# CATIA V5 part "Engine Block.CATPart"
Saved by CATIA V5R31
Part number: Part1
Bounding box of the stored display mesh (mm): x 0 to 150, y 0 to 40, z 0 to 43
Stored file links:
  D:\PROJECTS\Project 2021\US EDITION\CATIA V5 6R 2021\Resources\Tutorial Files\c19_catia_v5_6r2021_tut\C19_tut_04.CATPart\Engine Block.CATPart
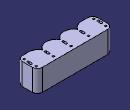
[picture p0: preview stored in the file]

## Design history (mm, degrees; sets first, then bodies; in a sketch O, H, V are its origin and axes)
Body1 (main body)
  Sketch1 on xy-plane, origin (0, 0, 0), H (1, 0, 0), V (0, 1, 0)
    line L1 (10, 0) -> (140, 0)
    line L2 (150, 10) -> (150, 30)
    line L3 (140, 40) -> (10, 40)
    line L4 (0, 30) -> (0, 10)
    arc A1 centre (10, 10) radius 10 from (10, 0) to (0, 10) cw
    arc A2 centre (140, 10) radius 10 from (140, 0) to (150, 10) ccw
    arc A3 centre (140, 30) radius 10 from (150, 30) to (140, 40) ccw
    arc A4 centre (10, 30) radius 10 from (10, 40) to (0, 30) ccw
    radius A1 = 10
    radius A2 = 10
    radius A3 = 10
    radius A4 = 10
    distance L2 L4 = 150
    distance L3 L1 = 40
    horizontal: L1 H, L3 H
    vertical: L2 V, L4 V
    coincidence: L1 O, L4 O
    tangency: A1 L1, A1 L4, A2 L1, A2 L2, A3 L2, A3 L3, A4 L3, A4 L4
  Pad1: profile Sketch1, direction (0, 0, 1), length 43
  Sketch2 on xy-plane, origin (0, 0, 0), H (1, 0, 0), V (0, 1, 0)
    circle A1 centre (22.5, 20) radius 12.5
    point P1 (22.5, 20)
    point P2 (57.5, 20)
    circle A2 centre (57.5, 20) radius 12.5
    point P3 (92.5, 20)
    circle A3 centre (92.5, 20) radius 12.5
    point P4 (127.5, 20)
    circle A4 centre (127.5, 20) radius 12.5
    reference projected line E1 (140, 40) -> (10, 40) from edge [face of Pad1 from Sketch1.L3 | end face of Pad1]
    construction line L1 (22.5, 20) -> (160.4972, 20)
    axis line L2 (75, 83.7885) -> (75, -11.6317)
    reference projected line E2 (150, 10) -> (150, 30) from edge [face of Pad1 from Sketch1.L2 | end face of Pad1]
    reference projected line E3 (0, 30) -> (0, 10) from edge [face of Pad1 from Sketch1.L4 | end face of Pad1]
    radius A2 = 12.5
    radius A3 = 12.5
    radius A4 = 12.5
    distance P1 E1 = 20
    distance P1 P2 = 35
    distance P2 P3 = 35
    distance P3 P4 = 35
    horizontal: L1 H
    coincidence: L1 P2, L1 P3, P4 L1
    symmetry: E2 E3 L2, A4 A1 L2
  Pocket1: profile Sketch2, direction (0, 0, 1), length 40
  Sketch3 on start face of Pad1, origin (0, 0, 0), H (1, 0, 0), V (0, -1, 0)
    arc A1 centre (22.5, -20) radius 20 from (40, -10.3175) to (22.4999, 0) ccw
    arc A2 centre (57.5, -20) radius 20 from (57.5, 0) to (40, -10.3175) ccw
    reference projected circle E1 centre (57.5, -20) radius 12.5 from edge [face of Pocket1 from Sketch2.A2 | start face of Pad1]
    reference projected circle E2 centre (22.5, -20) radius 12.5 from edge [face of Pocket1 from Sketch2.A1 | start face of Pad1]
    line L1 (22.4999, 0) -> (57.5, 0)
    radius A1 = 20
    radius A2 = 20
    concentricity: A2 E1, E2 A1
    fix: L1
  Pocket2: profile Sketch3, direction (0, 0, 1), through (limit type 6)
  RectPattern1: of Pocket2, direction 1 instances 3, spacing 35, along edge [start face of Pad1 | face of Pad1 from Sketch1.L1]
  Sketch4 on start face of Pad1, origin (0, 0, 0), H (1, 0, 0), V (0, -1, 0)
    circle A1 centre (6, -32) radius 2
    point P2 (40, -32)
    circle A2 centre (40, -32) radius 2
    point P3 (75, -32)
    circle A3 centre (75, -32) radius 2
    point P4 (110, -32)
    circle A4 centre (110, -32) radius 2
    circle A5 centre (144, -32) radius 2
    construction line L1 (6, -32) -> (144, -32)
    construction line L2 (40, 4.6658) -> (40, -59.1562)
    reference projected point E1 (40, -10.3175) from vertex [start face of Pad1 | face of Pocket2 from Sketch3.A2 | face of Pocket2 from Sketch3.A1]
    construction line L3 (110, 9.612) -> (110, -55.4864)
    construction line L4 (75, 52.0631) -> (75, -75.4722)
    reference projected line E2 (0, -30) -> (0, -10) from edge [start face of Pad1 | face of Pad1 from Sketch1.L4]
    reference projected line E3 (150, -10) -> (150, -30) from edge [start face of Pad1 | face of Pad1 from Sketch1.L2]
    reference projected point E4 (110, -10.3175) from vertex [face of RectPattern1 | face of RectPattern1 | start face of Pad1]
    axis line L5 (-9.2648, -20) -> (155.2665, -20)
    reference projected line E5 (10, 0) -> (140, 0) from edge [start face of Pad1 | face of Pad1 from Sketch1.L1]
    reference projected line E6 (140, -40) -> (10, -40) from edge [start face of Pad1 | face of Pad1 from Sketch1.L3]
    circle A6 centre (6, -8) radius 2
    circle A7 centre (144, -8) radius 2
    radius A1 = 2
    radius A2 = 2
    radius A3 = 2
    radius A4 = 2
    horizontal: L1 H, L5 H
    coincidence: P4 L1, P3 L1, P2 L1, L2 E1, P2 L2, P4 L3, P3 L4, L3 E4
    vertical: L2 V, L3 V, L4 V
    symmetry: E2 E3 L4, A1 A5 L4, E5 E6 L5, A1 A6 L5, A5 A7 L5
    fix: A1
  Pocket3: profile Sketch4, direction (0, 0, 1), through (limit type 6)
  Sketch5 on start face of Pad1, origin (0, 0, 0), H (1, 0, 0), V (0, -1, 0)
    construction line L1 (40, -22.3175) -> (40, -16.3175)
    point P2 (40, -16.3175)
    line L2 (38, -22.3175) -> (38, -16.3175)
    line L3 (42, -16.3175) -> (42, -22.3175)
    arc A1 centre (40, -16.3175) radius 2 from (38, -16.3175) to (42, -16.3175) cw
    arc A2 centre (40, -22.3175) radius 2 from (42, -22.3175) to (38, -22.3175) cw
    point P3 (38, -22.3175)
    point P4 (38, -16.3175)
    point P5 (42, -16.3175)
    point P6 (42, -22.3175)
    reference projected point E1 (40, -10.3175) from vertex [start face of Pad1 | face of Pocket2 from Sketch3.A2 | face of Pocket2 from Sketch3.A1]
    reference projected point E2 (40, -10.3175) from vertex [start face of Pad1 | face of Pocket2 from Sketch3.A2 | face of Pocket2 from Sketch3.A1]
    point P7 (75, -16.3175)
    point P8 (75, -22.3175)
    construction line L4 (75, -22.3175) -> (75, -16.3175)
    point P9 (73, -22.3175)
    point P10 (73, -16.3175)
    point P11 (77, -16.3175)
    point P12 (77, -22.3175)
    line L5 (73, -22.3175) -> (73, -16.3175)
    line L6 (77, -16.3175) -> (77, -22.3175)
    arc A3 centre (75, -16.3175) radius 2 from (73, -16.3175) to (77, -16.3175) cw
    arc A4 centre (75, -22.3175) radius 2 from (77, -22.3175) to (73, -22.3175) cw
    reference projected point E3 (75, -10.3175) from vertex [face of RectPattern1 | face of RectPattern1 | start face of Pad1]
    construction line L7 (110, -22.3175) -> (110, -16.3175)
    point P15 (112, -22.3175)
    point P16 (112, -16.3175)
    point P17 (108, -16.3175)
    point P18 (108, -22.3175)
    line L8 (112, -22.3175) -> (112, -16.3175)
    line L9 (108, -16.3175) -> (108, -22.3175)
    arc A5 centre (110, -16.3175) radius 2 from (112, -16.3175) to (108, -16.3175) ccw
    arc A6 centre (110, -22.3175) radius 2 from (108, -22.3175) to (112, -22.3175) ccw
    reference projected point E4 (75, -10.3175) from vertex [face of RectPattern1 | face of RectPattern1 | start face of Pad1]
    axis line L10 (40, -22.3175) -> (110, -22.3175)
    construction line L11 (5, -22.3175) -> (5, -16.3175)
    point P21 (7, -22.3175)
    point P22 (7, -16.3175)
    point P23 (3, -16.3175)
    point P24 (3, -22.3175)
    line L12 (7, -22.3175) -> (7, -16.3175)
    line L13 (3, -16.3175) -> (3, -22.3175)
    arc A7 centre (5, -16.3175) radius 2 from (7, -16.3175) to (3, -16.3175) ccw
    arc A8 centre (5, -22.3175) radius 2 from (3, -22.3175) to (7, -22.3175) ccw
    construction line L14 (145, -22.3175) -> (145, -16.3175)
    point P27 (147, -22.3175)
    point P28 (147, -16.3175)
    point P29 (143, -16.3175)
    point P30 (143, -22.3175)
    line L15 (147, -22.3175) -> (147, -16.3175)
    line L16 (143, -16.3175) -> (143, -22.3175)
    arc A9 centre (145, -16.3175) radius 2 from (147, -16.3175) to (143, -16.3175) ccw
    arc A10 centre (145, -22.3175) radius 2 from (143, -22.3175) to (147, -22.3175) ccw
    distance L1 L2 = 2
    length L1 = 6
    distance P2 E2 = 6
    distance P7 E4 = 6
    radius A3 = 2
    distance L5 L6 = 4
    vertical: L1 V
    tangency: A1 L2, A2 L2, A1 L3, A2 L3
    coincidence: L1 E1, L4 E3, L10 P8
    symmetry: L1 L7 L4, P3 P15 L4, P4 P16 L4, P5 P17 L4, P6 P18 L4, L2 L8 L4, L3 L9 L4, A1 A5 L4, A2 A6 L4, L4 L11 L1, P9 P21 L1, P10 P22 L1, P11 P23 L1, P12 P24 L1, L5 L12 L1, L6 L13 L1, A3 A7 L1, A4 A8 L1, L4 L14 L7, P9 P27 L7, P10 P28 L7, P11 P29 L7, P12 P30 L7, L5 L15 L7, L6 L16 L7, A3 A9 L7, A4 A10 L7
    horizontal: L10 H
  Pocket4: profile Sketch5, direction (0, 0, 1), through (limit type 6)
  Sketch6 on start face of Pad1, origin (0, 0, 0), H (1, 0, 0), V (0, -1, 0)
    construction line L1 (-2.1155, -20) -> (152.3983, -20)
    reference projected line E1 (10, 0) -> (140, 0) from edge [start face of Pad1 | face of Pad1 from Sketch1.L1]
    reference projected line E2 (140, -40) -> (10, -40) from edge [start face of Pad1 | face of Pad1 from Sketch1.L3]
    circle A1 centre (22, -4) radius 1.5
    point P3 (22, -4)
    circle A2 centre (22, -36) radius 1.5
    construction line L2 (40, 18.8361) -> (40, -51.6721)
    reference projected point E3 (40, -10.3175) from vertex [start face of Pad1 | face of RectPattern1 | face of Pocket2 from Sketch3.A1]
    circle A3 centre (58, -4) radius 1.5
    axis line L3 (75, 12.6867) -> (75, -50.2038)
    reference projected point E4 (75, -10.3175) from vertex [face of RectPattern1 | face of RectPattern1 | start face of Pad1]
    circle A4 centre (58, -36) radius 1.5
    circle A5 centre (128, -4) radius 1.5
    circle A6 centre (128, -36) radius 1.5
    circle A7 centre (92, -36) radius 1.5
    circle A8 centre (92, -4) radius 1.5
    radius A1 = 1.5
    distance P3 V = 22
    distance P3 L1 = 16
    horizontal: L1 H
    symmetry: E1 E2 L1, A1 A2 L1, A1 A3 L2, A2 A4 L2, A1 A5 L3, A2 A6 L3, A4 A7 L3, A3 A8 L3
    vertical: L2 V, L3 V
    coincidence: E3 L2, L3 E4
  Pocket5: profile Sketch6, direction (0, 0, 1), length 10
